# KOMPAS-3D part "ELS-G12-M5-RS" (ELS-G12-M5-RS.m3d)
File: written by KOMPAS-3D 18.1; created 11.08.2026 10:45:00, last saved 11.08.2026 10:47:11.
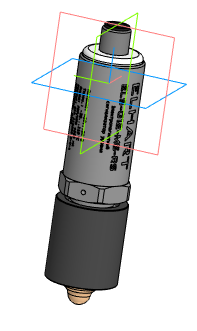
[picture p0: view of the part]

Document properties: Полное имя файла: Z:\Элхарт\КД\КД.ЭЛХТ-Д (Датчики)\КД.ЭЛХТ-ДУ (Датчики уровня)\КД.ЭЛХТ-ДУ03 (эл.маг. сигнализатор ур-ня)\КД.ЭЛХТ-ДУ03-М.01\Для сайта\ELS-G12-M5-RS_1.m3d

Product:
- Part/product: ELS-G12-M5-RS
    Масса: 0.31375
  - Body: Тело 12
      Масса: 0.114052
  - Body: Тело 11
      Масса: 0.00170578
  - Body: Тело 10
      Масса: 0.00170578
  - Body: Тело 9
      Масса: 0.0929602
  - Body: Тело 8
      Масса: 0.0010855
  - Body: Тело 7
      Масса: 0.0128321
  - Body: Тело 6
      Масса: 0.00496287
  - Body: Тело 5
      Масса: 0.000300607
  - Body: Тело 4
      Масса: 0.000174455
  - Body: Тело 3
      Масса: 0.000232607
  - Body: Тело 2
      Масса: 0.057816
  - Body: Тело 1
      Масса: 0.0259222

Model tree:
1. Операция без истории:1
2. Операция без истории:2
3. Операция без истории:3
4. Операция без истории:4
5. Операция без истории:5
6. Операция без истории:6
7. Операция без истории:7
8. Операция без истории:8
9. Операция без истории:9
10. Операция без истории:10
11. Операция без истории:11
12. Операция без истории:12
13. Поверхность без истории:1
